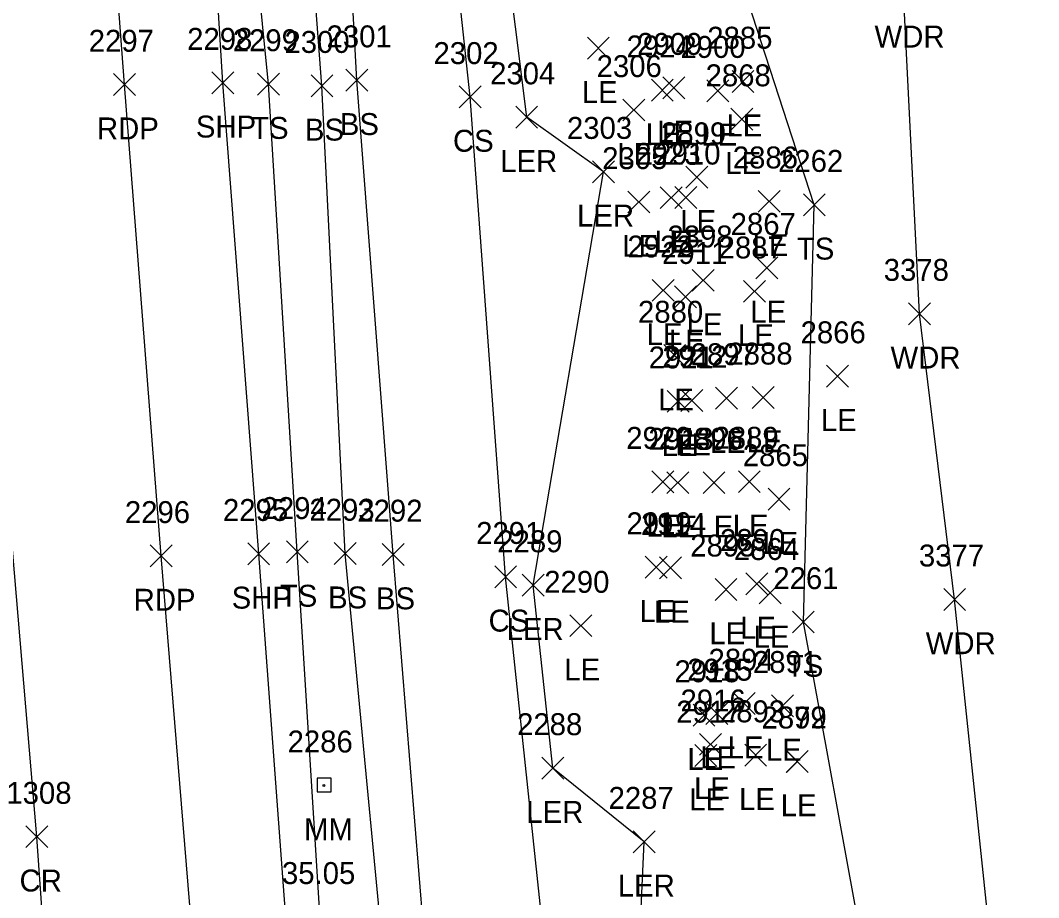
# Model space of a CAD drawing. Extents: x 1650221 to 1650634, y 244606 to 249996.
# Drawn here: x 1650345.1 to 1650438, y 246477.6 to 246557.6 of the extents above; entities that cross this region are included whole.
import ezdxf

# ---------------------------------------------------------------- set-up
doc = ezdxf.new("R2010")
doc.units = 0
for name, color, linetype in [('L_A', 7, 'Continuous'), ('L_I', 7, 'Continuous'), ('L_TIC', 7, 'Continuous'), ('LARO', 7, 'Continuous'), ('LAWA', 7, 'Continuous'), ('LELB', 7, 'Continuous'), ('P_A', 7, 'Continuous'), ('P_I', 7, 'Continuous'), ('P_TIC', 7, 'Continuous'), ('PET', 7, 'Continuous'), ('PRC', 7, 'Continuous'), ('PSP', 7, 'Continuous'), ('S_A', 7, 'Continuous'), ('S_C', 7, 'Continuous'), ('S_I', 7, 'Continuous'), ('SRM', 7, 'Continuous')]:
    doc.layers.add(name, color=color, linetype=linetype)

msp = doc.modelspace()

# ---------------------------------------------------------------- linework, layer by layer
at = {"layer": 'L_TIC'}
for points in [[(1650396.825, 246554.059), (1650398.825, 246556.059)], [(1650398.825, 246554.059), (1650396.825, 246556.059)], [(1650374.792, 246551.139), (1650376.792, 246553.139)], [(1650376.792, 246551.139), (1650374.792, 246553.139)], [(1650410.023, 246551.016), (1650412.023, 246553.016)], [(1650412.023, 246551.016), (1650410.023, 246553.016)], [(1650366.729, 246550.788), (1650368.729, 246552.788)], [(1650368.729, 246550.788), (1650366.729, 246552.788)], [(1650371.604, 246550.632), (1650373.604, 246552.632)], [(1650373.604, 246550.632), (1650371.604, 246552.632)], [(1650402.661, 246550.221), (1650404.661, 246552.221)], [(1650404.661, 246550.221), (1650402.661, 246552.221)], [(1650403.714, 246550.45), (1650405.714, 246552.45)], [(1650405.714, 246550.45), (1650403.714, 246552.45)], [(1650407.734, 246550.176), (1650409.734, 246552.176)], [(1650409.734, 246550.176), (1650407.734, 246552.176)], [(1650385.116, 246549.614), (1650387.116, 246551.614)], [(1650387.116, 246549.614), (1650385.116, 246551.614)], [(1650400.058, 246548.424), (1650402.058, 246550.424)], [(1650402.058, 246548.424), (1650400.058, 246550.424)], [(1650390.282, 246547.764), (1650392.282, 246549.764)], [(1650392.282, 246547.764), (1650390.282, 246549.764)], [(1650409.916, 246547.587), (1650411.916, 246549.587)], [(1650411.916, 246547.587), (1650409.916, 246549.587)], [(1650397.297, 246542.788), (1650399.297, 246544.788)], [(1650399.297, 246542.788), (1650397.297, 246544.788)], [(1650405.809, 246542.293), (1650407.809, 246544.293)], [(1650407.809, 246542.293), (1650405.809, 246544.293)], [(1650400.513, 246540.03), (1650402.513, 246542.03)], [(1650402.513, 246540.03), (1650400.513, 246542.03)], [(1650403.464, 246540.422), (1650405.464, 246542.422)], [(1650405.464, 246540.422), (1650403.464, 246542.422)], [(1650404.801, 246540.447), (1650406.801, 246542.447)], [(1650406.801, 246540.447), (1650404.801, 246542.447)], [(1650412.404, 246540.093), (1650414.404, 246542.093)], [(1650414.404, 246540.093), (1650412.404, 246542.093)], [(1650416.529, 246539.777), (1650418.529, 246541.777)], [(1650418.529, 246539.777), (1650416.529, 246541.777)], [(1650412.204, 246534.028), (1650414.204, 246536.028)], [(1650414.204, 246534.028), (1650412.204, 246536.028)], [(1650406.382, 246532.881), (1650408.382, 246534.881)], [(1650408.382, 246532.881), (1650406.382, 246534.881)], [(1650402.738, 246531.969), (1650404.738, 246533.969)], [(1650404.738, 246531.969), (1650402.738, 246533.969)], [(1650411.063, 246531.883), (1650413.063, 246533.883)], [(1650413.063, 246531.883), (1650411.063, 246533.883)], [(1650404.768, 246531.38), (1650406.768, 246533.38)], [(1650406.768, 246531.38), (1650404.768, 246533.38)], [(1650426.125, 246529.837), (1650428.125, 246531.837)], [(1650428.125, 246529.837), (1650426.125, 246531.837)], [(1650403.787, 246526.015), (1650405.787, 246528.015)], [(1650405.787, 246526.015), (1650403.787, 246528.015)], [(1650418.639, 246524.14), (1650420.639, 246526.14)], [(1650420.639, 246524.14), (1650418.639, 246526.14)], [(1650408.51, 246522.142), (1650410.51, 246524.142)], [(1650410.51, 246522.142), (1650408.51, 246524.142)], [(1650411.861, 246522.2), (1650413.861, 246524.2)], [(1650413.861, 246522.2), (1650411.861, 246524.2)], [(1650404.11, 246521.846), (1650406.11, 246523.846)], [(1650406.11, 246521.846), (1650404.11, 246523.846)], [(1650405.348, 246521.924), (1650407.348, 246523.924)], [(1650407.348, 246521.924), (1650405.348, 246523.924)], [(1650402.712, 246514.51), (1650404.712, 246516.51)], [(1650404.712, 246514.51), (1650402.712, 246516.51)], [(1650404.077, 246514.424), (1650406.077, 246516.424)], [(1650406.077, 246514.424), (1650404.077, 246516.424)], [(1650407.375, 246514.426), (1650409.375, 246516.426)], [(1650409.375, 246514.426), (1650407.375, 246516.426)], [(1650410.598, 246514.518), (1650412.598, 246516.518)], [(1650412.598, 246514.518), (1650410.598, 246516.518)], [(1650413.308, 246512.927), (1650415.308, 246514.927)], [(1650415.308, 246512.927), (1650413.308, 246514.927)], [(1650369.351, 246508.107), (1650371.351, 246510.107)], [(1650371.351, 246508.107), (1650369.351, 246510.107)], [(1650373.717, 246507.954), (1650375.717, 246509.954)], [(1650375.717, 246507.954), (1650373.717, 246509.954)], [(1650378.089, 246507.869), (1650380.089, 246509.869)], [(1650380.089, 246507.869), (1650378.089, 246509.869)], [(1650402.088, 246506.719), (1650404.088, 246508.719)], [(1650404.088, 246506.719), (1650402.088, 246508.719)], [(1650403.4, 246506.653), (1650405.4, 246508.653)], [(1650405.4, 246506.653), (1650403.4, 246508.653)], [(1650388.364, 246505.838), (1650390.364, 246507.838)], [(1650390.364, 246505.838), (1650388.364, 246507.838)], [(1650390.868, 246505.076), (1650392.868, 246507.076)], [(1650392.868, 246505.076), (1650390.868, 246507.076)], [(1650408.468, 246504.686), (1650410.468, 246506.686)], [(1650410.468, 246504.686), (1650408.468, 246506.686)], [(1650411.276, 246505.193), (1650413.276, 246507.193)], [(1650413.276, 246505.193), (1650411.276, 246507.193)], [(1650412.496, 246504.373), (1650414.496, 246506.373)], [(1650414.496, 246504.373), (1650412.496, 246506.373)], [(1650429.335, 246503.777), (1650431.335, 246505.777)], [(1650431.335, 246503.777), (1650429.335, 246505.777)], [(1650415.532, 246501.712), (1650417.532, 246503.712)], [(1650417.532, 246501.712), (1650415.532, 246503.712)], [(1650395.231, 246501.377), (1650397.231, 246503.377)], [(1650397.231, 246501.377), (1650395.231, 246503.377)], [(1650410.137, 246494.27), (1650412.137, 246496.27)], [(1650412.137, 246494.27), (1650410.137, 246496.27)], [(1650407.627, 246493.36), (1650409.627, 246495.36)], [(1650409.627, 246493.36), (1650407.627, 246495.36)], [(1650413.622, 246494.062), (1650415.622, 246496.062)], [(1650415.622, 246494.062), (1650413.622, 246496.062)], [(1650406.461, 246493.218), (1650408.461, 246495.218)], [(1650408.461, 246493.218), (1650406.461, 246495.218)], [(1650407.068, 246490.553), (1650409.068, 246492.553)], [(1650409.068, 246490.553), (1650407.068, 246492.553)], [(1650406.624, 246489.537), (1650408.624, 246491.537)], [(1650408.624, 246489.537), (1650406.624, 246491.537)], [(1650411.176, 246489.562), (1650413.176, 246491.562)], [(1650413.176, 246489.562), (1650411.176, 246491.562)], [(1650414.977, 246488.998), (1650416.977, 246490.998)], [(1650416.977, 246488.998), (1650414.977, 246490.998)], [(1650414.979, 246488.996), (1650416.979, 246490.996)], [(1650416.979, 246488.996), (1650414.979, 246490.996)], [(1650392.668, 246488.39), (1650394.668, 246490.39)], [(1650394.668, 246488.39), (1650392.668, 246490.39)], [(1650401.014, 246481.667), (1650403.014, 246483.667)], [(1650403.014, 246481.667), (1650401.014, 246483.667)]]:
    msp.add_lwpolyline(points, dxfattribs=at)
at = {"layer": 'LARO'}
msp.add_lwpolyline([(1650408.62, 246217.57), (1650415.017, 246258.551), (1650416.029, 246285.891), (1650409.424, 246296.822), (1650403.385, 246341.569), (1650407.268, 246374.549), (1650399.81, 246378.857), (1650397.578, 246413.378), (1650396.61, 246418.121), (1650404.549, 246441.775), (1650400.932, 246459.086), (1650402.014, 246482.667), (1650393.668, 246489.39), (1650391.868, 246506.076), (1650398.297, 246543.788), (1650391.282, 246548.764), (1650385.03, 246598.745), (1650385.051, 246648.918)], dxfattribs=at)
at = {"layer": 'LAWA'}
msp.add_lwpolyline([(1650467.45, 246241.248), (1650457.439, 246253.738), (1650465.182, 246273.586), (1650462.121, 246310.217), (1650448.311, 246306.896), (1650448.47, 246334.537), (1650451.184, 246360.806), (1650449.397, 246391.825), (1650443.671, 246414.288), (1650436.755, 246442.34), (1650433.959, 246470.022), (1650430.335, 246504.777), (1650427.125, 246530.837), (1650425.665, 246560.118), (1650421.393, 246581.34), (1650411.429, 246590.247), (1650407.773, 246596.466), (1650408.993, 246611.27), (1650406.472, 246635.271)], dxfattribs=at)
at = {"layer": 'LELB'}
for points in [[(1650393.271, 246215.062), (1650388.589, 246258.034), (1650385.303, 246297.22), (1650382.892, 246338.269), (1650379.783, 246382.543), (1650376.697, 246415.11), (1650373.391, 246460.521), (1650370.351, 246509.107), (1650367.729, 246551.788), (1650362.786, 246601.351), (1650360.906, 246643.926), (1650360.73, 246683.447), (1650355.99, 246728.594), (1650353.015, 246770.02), (1650352.21, 246793.578), (1650347.695, 246827.184)], [(1650406.656, 246218.25), (1650409.738, 246258.013), (1650404.964, 246296.74), (1650400.855, 246340.502), (1650395.586, 246379.715), (1650393.167, 246415.096), (1650394.545, 246457.778), (1650389.364, 246506.838), (1650386.116, 246550.614), (1650380.924, 246598.971), (1650378.983, 246645.95), (1650376.234, 246684.957), (1650377.195, 246729.688), (1650373.963, 246768.954), (1650374.901, 246794.969)], [(1650398.424, 246215.354), (1650393.502, 246258.252), (1650390.33, 246297.072), (1650387.572, 246339.17), (1650383.093, 246382.589), (1650381.544, 246415.749), (1650379.325, 246460.798), (1650374.717, 246508.954), (1650372.604, 246551.632), (1650368.85, 246601.305), (1650366.306, 246644.434), (1650364.471, 246684.577), (1650363.627, 246728.256), (1650358.66, 246769.405), (1650355.434, 246788.128), (1650360.397, 246788.442)], [(1650402.25, 246216.694), (1650398.468, 246258.758), (1650395.79, 246297.148), (1650391.97, 246340.099), (1650387.542, 246382.066), (1650385.712, 246415.977), (1650383.049, 246460.21), (1650379.089, 246508.869), (1650375.792, 246552.139), (1650373.138, 246601), (1650370.951, 246644.961), (1650368.354, 246684.963), (1650367.995, 246727.841), (1650362.742, 246769.205), (1650360.397, 246788.442)], [(1650445.175, 246217.398), (1650445.531, 246269.295), (1650441.896, 246297.748), (1650443.518, 246304.658), (1650437.793, 246334.622), (1650435.282, 246374.906), (1650430.354, 246416.998), (1650432.132, 246431.963), (1650424.254, 246446.431), (1650422.05, 246472.523), (1650416.532, 246502.712), (1650417.529, 246540.777), (1650409.477, 246565.503), (1650407.868, 246589.874), (1650402.921, 246599.271), (1650397.783, 246634.795)]]:
    msp.add_lwpolyline(points, dxfattribs=at)
at = {"layer": 'P_TIC'}
for points in [[(1650353.58, 246550.739), (1650355.58, 246552.739)], [(1650355.58, 246550.739), (1650353.58, 246552.739)], [(1650362.56, 246550.911), (1650364.56, 246552.911)], [(1650364.56, 246550.911), (1650362.56, 246552.911)], [(1650356.931, 246507.739), (1650358.931, 246509.739)], [(1650358.931, 246507.739), (1650356.931, 246509.739)], [(1650365.828, 246507.934), (1650367.828, 246509.934)], [(1650367.828, 246507.934), (1650365.828, 246509.934)], [(1650345.572, 246482.126), (1650347.572, 246484.126)], [(1650347.572, 246482.126), (1650345.572, 246484.126)]]:
    msp.add_lwpolyline(points, dxfattribs=at)
at = {"layer": 'PET'}
msp.add_lwpolyline([(1650378.627, 246214.911), (1650375.804, 246256.561), (1650373.007, 246296.437), (1650370.077, 246336.196), (1650366.982, 246382.901), (1650364.952, 246414.805), (1650361.941, 246459.783), (1650357.931, 246508.739), (1650354.58, 246551.739), (1650350.862, 246600.915), (1650347.478, 246643.699), (1650346.095, 246667.406)], dxfattribs=at)
at = {"layer": 'PRC'}
msp.add_lwpolyline([(1650365.1, 246222.227), (1650362.037, 246265.668), (1650358.205, 246317.529), (1650354.885, 246368.983), (1650350.401, 246428.864), (1650346.572, 246483.126), (1650341.975, 246537.02), (1650338.566, 246591.04), (1650334.55, 246647.319), (1650330.715, 246698.073), (1650326.818, 246753.453), (1650322.926, 246808.73), (1650318.78, 246866.298), (1650315.63, 246915.252), (1650311.692, 246971.177), (1650308.09, 247021.187), (1650305.21, 247068.939), (1650301.6, 247120.361), (1650298.797, 247160.796), (1650294.821, 247207.202), (1650291.445, 247257.785)], dxfattribs=at)
at = {"layer": 'PSP'}
msp.add_lwpolyline([(1650388.25, 246215.072), (1650385.023, 246257.594), (1650382.118, 246297.012), (1650379.042, 246337.668), (1650376.285, 246382.909), (1650373.452, 246415.126), (1650370.449, 246460.184), (1650366.828, 246508.934), (1650363.56, 246551.911), (1650360.5, 246601.385), (1650356.679, 246643.626), (1650355.129, 246668.21)], dxfattribs=at)
at = {"layer": 'SRM'}
for p, q in [((1650373.429, 246488.465), (1650372.179, 246488.465)), ((1650372.179, 246488.465), (1650372.179, 246487.215)), ((1650373.429, 246488.465), (1650372.179, 246488.465)), ((1650372.179, 246488.465), (1650372.179, 246487.215)), ((1650373.429, 246487.215), (1650373.429, 246488.465)), ((1650373.429, 246487.215), (1650373.429, 246488.465)), ((1650372.179, 246487.215), (1650373.429, 246487.215)), ((1650372.179, 246487.215), (1650373.429, 246487.215))]:
    msp.add_line(p, q, dxfattribs=at)
msp.add_circle((1650372.78, 246487.803), 0.0833, dxfattribs=at)

# ---------------------------------------------------------------- texts
at = {"layer": 'L_A'}
for s, p in [('WDR', (1650423.027, 246555.118)), ('LE', (1650396.314, 246550.059)), ('TS', (1650366.139, 246546.788)), ('BS', (1650371.045, 246546.632)), ('BS', (1650374.233, 246547.139)), ('LE', (1650403.202, 246546.45)), ('LE', (1650409.511, 246547.016)), ('CS', (1650384.557, 246545.614)), ('LE', (1650402.149, 246546.221)), ('LE', (1650407.222, 246546.176)), ('LE', (1650399.546, 246544.424)), ('LER', (1650388.865, 246543.764)), ('LE', (1650409.405, 246543.587)), ('LER', (1650395.88, 246538.788)), ('LE', (1650405.297, 246538.293)), ('LE', (1650402.952, 246536.422)), ('LE', (1650404.289, 246536.447)), ('LE', (1650411.892, 246536.093)), ('LE', (1650400.001, 246536.03)), ('TS', (1650415.938, 246535.777)), ('LE', (1650411.693, 246530.028)), ('LE', (1650405.871, 246528.881)), ('LE', (1650402.226, 246527.969)), ('LE', (1650410.552, 246527.883)), ('LE', (1650404.256, 246527.38)), ('WDR', (1650424.487, 246525.837)), ('LE', (1650403.276, 246522.015)), ('LE', (1650418.127, 246520.14)), ('LE', (1650403.598, 246517.846)), ('LE', (1650404.836, 246517.924)), ('LE', (1650407.998, 246518.142)), ('LE', (1650411.35, 246518.2)), ('LE', (1650402.201, 246510.51)), ('LE', (1650403.565, 246510.424)), ('LE', (1650406.864, 246510.426)), ('LE', (1650410.086, 246510.518)), ('LE', (1650412.796, 246508.927)), ('TS', (1650368.761, 246504.107)), ('BS', (1650373.158, 246503.954)), ('BS', (1650377.53, 246503.869)), ('LE', (1650401.576, 246502.719)), ('LE', (1650402.888, 246502.653)), ('CS', (1650387.805, 246501.838)), ('LER', (1650389.451, 246501.076)), ('LE', (1650410.764, 246501.193)), ('LE', (1650407.956, 246500.686)), ('LE', (1650411.984, 246500.373)), ('WDR', (1650427.697, 246499.777)), ('LE', (1650394.719, 246497.377)), ('TS', (1650414.941, 246497.712)), ('LE', (1650409.625, 246490.27)), ('LE', (1650413.11, 246490.062)), ('LE', (1650405.949, 246489.218)), ('LE', (1650407.115, 246489.36)), ('LE', (1650406.556, 246486.553)), ('LE', (1650406.112, 246485.537)), ('LE', (1650410.664, 246485.562)), ('LE', (1650414.466, 246484.998)), ('LE', (1650414.467, 246484.996)), ('LER', (1650391.25, 246484.39)), ('LER', (1650399.597, 246477.667))]:
    msp.add_text(s, height=2, dxfattribs=at).set_placement(p)
at = {"layer": 'L_I'}
for s, p in [('2299', (1650364.461, 246554.788)), ('2300', (1650369.179, 246554.632)), ('2301', (1650373.02, 246555.139)), ('2885', (1650407.763, 246555.016)), ('2924', (1650400.401, 246554.221)), ('2909', (1650401.367, 246554.45)), ('2900', (1650405.309, 246554.176)), ('2302', (1650382.777, 246553.614)), ('2306', (1650397.664, 246552.424)), ('2304', (1650387.944, 246551.764)), ('2868', (1650407.609, 246551.587)), ('2303', (1650394.959, 246546.788)), ('2899', (1650403.541, 246546.293)), ('2923', (1650401.204, 246544.422)), ('2910', (1650403.022, 246544.447)), ('2305', (1650398.174, 246544.03)), ('2886', (1650410.089, 246544.093)), ('2262', (1650414.222, 246543.777)), ('2867', (1650409.897, 246538.028)), ('2898', (1650404.123, 246536.881)), ('2922', (1650400.478, 246535.969)), ('2911', (1650403.642, 246535.38)), ('2887', (1650408.803, 246535.883)), ('3378', (1650423.865, 246533.837)), ('2880', (1650401.441, 246530.015)), ('2866', (1650416.277, 246528.14)), ('2921', (1650402.417, 246525.846)), ('2912', (1650403.655, 246525.924)), ('2897', (1650406.25, 246526.142)), ('2888', (1650409.601, 246526.2)), ('2920', (1650400.366, 246518.51)), ('2913', (1650402.384, 246518.424)), ('2896', (1650405.06, 246518.426)), ('2889', (1650408.33, 246518.518)), ('2865', (1650411.001, 246516.927)), ('2294', (1650367.091, 246512.107)), ('2293', (1650371.457, 246511.954)), ('2292', (1650375.83, 246511.869)), ('2919', (1650400.387, 246510.719)), ('2914', (1650401.707, 246510.653)), ('2291', (1650386.672, 246509.838)), ('2890', (1650408.929, 246509.193)), ('2289', (1650388.6, 246509.076)), ('2895', (1650406.208, 246508.686)), ('2864', (1650410.189, 246508.373)), ('3377', (1650427.075, 246507.777)), ('2290', (1650392.884, 246505.377)), ('2261', (1650413.792, 246505.712)), ('2894', (1650407.877, 246498.27)), ('2891', (1650411.929, 246498.062)), ('2918', (1650404.768, 246497.218)), ('2915', (1650405.934, 246497.36)), ('2916', (1650405.32, 246494.553)), ('2917', (1650404.931, 246493.537)), ('2893', (1650408.916, 246493.562)), ('2288', (1650390.408, 246492.39)), ('2879', (1650412.711, 246492.996)), ('2892', (1650412.718, 246492.998)), ('2287', (1650398.754, 246485.667))]:
    msp.add_text(s, height=2, dxfattribs=at).set_placement(p)
at = {"layer": 'P_A'}
for s, p in [('RDP', (1650352.069, 246546.739)), ('SHP', (1650361.095, 246546.911)), ('RDP', (1650355.42, 246503.739)), ('SHP', (1650364.363, 246503.934)), ('CR', (1650345.005, 246478.126))]:
    msp.add_text(s, height=2, dxfattribs=at).set_placement(p)
at = {"layer": 'P_I'}
for s, p in [('2297', (1650351.32, 246554.739)), ('2298', (1650360.3, 246554.911)), ('2295', (1650363.568, 246511.934)), ('2296', (1650354.616, 246511.739)), ('1308', (1650343.8, 246486.126))]:
    msp.add_text(s, height=2, dxfattribs=at).set_placement(p)
at = {"layer": 'S_A'}
msp.add_text('MM', height=2, dxfattribs=at).set_placement((1650370.967, 246482.808))
at = {"layer": 'S_C'}
msp.add_text('35.05', height=2, dxfattribs=at).set_placement((1650368.952, 246478.808))
at = {"layer": 'S_I'}
msp.add_text('2286', height=2, dxfattribs=at).set_placement((1650369.464, 246490.808))

doc.saveas('drawing.dxf')
